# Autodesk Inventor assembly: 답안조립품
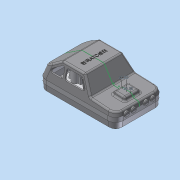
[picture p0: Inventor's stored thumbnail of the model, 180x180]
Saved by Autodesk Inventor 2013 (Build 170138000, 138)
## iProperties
Created: 2015-05
Part Number: 답안조립품
Document SubType Name: Assembly
Designer: Administrator
Author: Administrator
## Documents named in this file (7)
- C:\Users\Administrator\Desktop\450508V1049\답안조립품.iam
- C:\Users\Administrator\Desktop\450508V1049\본체.ipt
- C:\Users\Administrator\Desktop\450508V1049\M2x4.ipt
- C:\Users\Administrator\Desktop\450508V1049\M4x10.ipt
- C:\Users\Administrator\Desktop\450508V1049\바퀴.ipt
- C:\Users\Administrator\Desktop\450508V1049\바퀴고정부.ipt
- C:\Users\Administrator\Desktop\450508V1049\커버.ipt
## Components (17 placed, 2 different names)
1. M2x4:1
2. M4x10:1
3. M2x4:2
4. M2x4:3
5. M2x4:4
6. M2x4:5
7. M2x4:6
8. M2x4:7
9. M2x4:8
10. M2x4:9
11. M2x4:10
12. M2x4:11
13. M2x4:12
14. M2x4:13
15. M2x4:14
16. M2x4:15
17. M2x4:16
